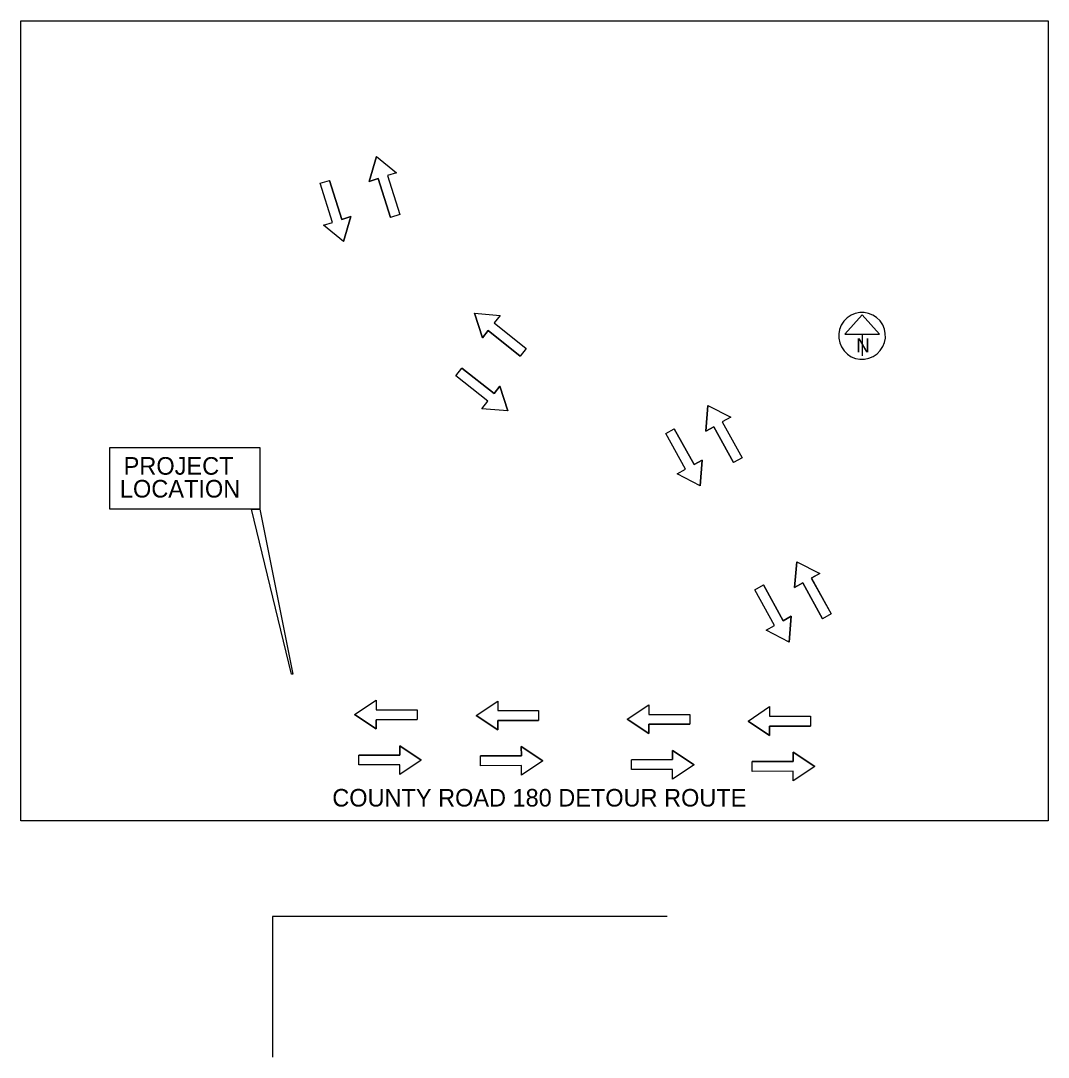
# Model space of a CAD drawing. Extents: x 1633.3 to 1707.6, y 1081.5 to 1106.
# Drawn here: x 1652.62 to 1670.85, y 1081.53 to 1099.94 of the extents above; entities that cross this region are included whole.
import ezdxf

# ---------------------------------------------------------------- set-up
doc = ezdxf.new("R2010")
doc.units = 0
for name, color, linetype in [('SH_Border', 7, 'Continuous'), ('SH_Data', 7, 'Continuous'), ('SH_Text', 7, 'Continuous')]:
    doc.layers.add(name, color=color, linetype=linetype)

msp = doc.modelspace()

# ---------------------------------------------------------------- linework, layer by layer
at = {"layer": 'SH_Border'}
for p, q in [((1664.087, 1084.034), (1657.087, 1084.034)), ((1657.087, 1084.034), (1657.087, 1081.534))]:
    msp.add_line(p, q, dxfattribs=at)
for points in [[(1652.616, 1099.936), (1670.853, 1099.936), (1670.853, 1085.731), (1652.616, 1085.731)], [(1654.195, 1092.36), (1656.86, 1092.36), (1656.86, 1091.264), (1654.195, 1091.264)], [(1656.86, 1091.264), (1657.447, 1088.337), (1657.424, 1088.335), (1656.711, 1091.264)]]:
    msp.add_lwpolyline(points, close=True, dxfattribs=at)
at = {"layer": 'SH_Data'}
for p, q in [((1667.548, 1094.714), (1667.241, 1094.372)), ((1667.856, 1094.372), (1667.548, 1094.714)), ((1667.241, 1094.372), (1667.856, 1094.372)), ((1667.548, 1094.372), (1667.548, 1093.986))]:
    msp.add_line(p, q, dxfattribs=at)
msp.add_arc((1667.548, 1094.34), 0.415, 129.7798, 129.7633, dxfattribs=at)
at = {"layer": 'SH_Text'}
for p, q in [((1658.929, 1097.525), (1658.802, 1097.083)), ((1658.929, 1097.525), (1659.287, 1097.237)), ((1658.802, 1097.083), (1658.958, 1097.133)), ((1658.958, 1097.133), (1659.177, 1096.44)), ((1659.287, 1097.237), (1659.124, 1097.185)), ((1659.124, 1097.185), (1659.342, 1096.493)), ((1657.931, 1097.049), (1658.097, 1097.101)), ((1658.15, 1096.356), (1657.931, 1097.049)), ((1658.316, 1096.409), (1658.097, 1097.101)), ((1658.472, 1096.458), (1658.316, 1096.409)), ((1658.344, 1096.017), (1658.472, 1096.458)), ((1659.342, 1096.493), (1659.177, 1096.44)), ((1657.987, 1096.305), (1658.15, 1096.356)), ((1658.344, 1096.017), (1657.987, 1096.305)), ((1660.668, 1094.742), (1661.126, 1094.704)), ((1660.668, 1094.742), (1660.81, 1094.305)), ((1661.126, 1094.704), (1661.019, 1094.57)), ((1661.019, 1094.57), (1661.588, 1094.119)), ((1660.81, 1094.305), (1660.911, 1094.434)), ((1660.911, 1094.434), (1661.48, 1093.983)), ((1661.588, 1094.119), (1661.48, 1093.983)), ((1660.339, 1093.631), (1660.447, 1093.768)), ((1660.908, 1093.18), (1660.339, 1093.631)), ((1661.016, 1093.317), (1660.447, 1093.768)), ((1661.118, 1093.445), (1661.016, 1093.317)), ((1661.26, 1093.008), (1661.118, 1093.445)), ((1660.802, 1093.046), (1660.908, 1093.18)), ((1664.809, 1093.106), (1664.773, 1092.648)), ((1664.809, 1093.106), (1665.217, 1092.896)), ((1661.26, 1093.008), (1660.802, 1093.046)), ((1665.217, 1092.896), (1665.068, 1092.812)), ((1664.773, 1092.648), (1664.916, 1092.728)), ((1664.916, 1092.728), (1665.269, 1092.093)), ((1665.068, 1092.812), (1665.421, 1092.178)), ((1664.064, 1092.607), (1664.216, 1092.692)), ((1664.417, 1091.973), (1664.064, 1092.607)), ((1664.569, 1092.057), (1664.216, 1092.692)), ((1665.421, 1092.178), (1665.269, 1092.093)), ((1664.268, 1091.89), (1664.417, 1091.973)), ((1664.712, 1092.137), (1664.569, 1092.057)), ((1664.676, 1091.679), (1664.712, 1092.137)), ((1664.676, 1091.679), (1664.268, 1091.89)), ((1666.389, 1090.332), (1666.352, 1089.874)), ((1666.389, 1090.332), (1666.797, 1090.122)), ((1666.352, 1089.874), (1666.495, 1089.954)), ((1666.495, 1089.954), (1666.848, 1089.319)), ((1666.797, 1090.122), (1666.648, 1090.039)), ((1666.648, 1090.039), (1667, 1089.404)), ((1665.644, 1089.834), (1665.796, 1089.918)), ((1665.997, 1089.199), (1665.644, 1089.834)), ((1666.149, 1089.284), (1665.796, 1089.918)), ((1667, 1089.404), (1666.848, 1089.319)), ((1666.292, 1089.363), (1666.149, 1089.284)), ((1666.256, 1088.905), (1666.292, 1089.363)), ((1665.847, 1089.116), (1665.997, 1089.199)), ((1666.256, 1088.905), (1665.847, 1089.116)), ((1658.542, 1087.616), (1658.924, 1087.871)), ((1658.924, 1087.871), (1658.925, 1087.7)), ((1660.699, 1087.603), (1661.081, 1087.858)), ((1661.081, 1087.858), (1661.082, 1087.687)), ((1663.382, 1087.535), (1663.764, 1087.79)), ((1663.764, 1087.79), (1663.765, 1087.619)), ((1665.524, 1087.502), (1665.906, 1087.758)), ((1665.906, 1087.758), (1665.906, 1087.587)), ((1658.542, 1087.616), (1658.925, 1087.363)), ((1658.925, 1087.7), (1659.651, 1087.702)), ((1659.651, 1087.702), (1659.651, 1087.528)), ((1660.699, 1087.603), (1661.082, 1087.349)), ((1661.082, 1087.687), (1661.808, 1087.689)), ((1661.808, 1087.689), (1661.808, 1087.515)), ((1663.765, 1087.619), (1664.491, 1087.621)), ((1664.491, 1087.621), (1664.491, 1087.447)), ((1665.906, 1087.587), (1666.632, 1087.588)), ((1666.632, 1087.588), (1666.633, 1087.414)), ((1658.925, 1087.526), (1659.651, 1087.528)), ((1658.925, 1087.363), (1658.925, 1087.526)), ((1661.082, 1087.513), (1661.808, 1087.515)), ((1661.082, 1087.349), (1661.082, 1087.513)), ((1663.382, 1087.535), (1663.765, 1087.282)), ((1663.765, 1087.445), (1664.491, 1087.447)), ((1663.765, 1087.282), (1663.765, 1087.445)), ((1665.524, 1087.502), (1665.907, 1087.249)), ((1665.907, 1087.413), (1666.633, 1087.414)), ((1665.907, 1087.249), (1665.907, 1087.413)), ((1659.726, 1086.809), (1659.343, 1087.062)), ((1659.343, 1087.062), (1659.344, 1086.899)), ((1661.883, 1086.796), (1661.5, 1087.049)), ((1661.5, 1087.049), (1661.501, 1086.885)), ((1659.344, 1086.899), (1658.618, 1086.897)), ((1658.618, 1086.723), (1658.618, 1086.897)), ((1661.501, 1086.885), (1660.775, 1086.884)), ((1660.775, 1086.71), (1660.775, 1086.884)), ((1664.567, 1086.728), (1664.184, 1086.981)), ((1664.184, 1086.981), (1664.184, 1086.818)), ((1666.708, 1086.695), (1666.325, 1086.949)), ((1666.325, 1086.949), (1666.326, 1086.785)), ((1659.344, 1086.724), (1658.618, 1086.723)), ((1659.345, 1086.554), (1659.344, 1086.724)), ((1659.726, 1086.809), (1659.345, 1086.554)), ((1661.501, 1086.711), (1660.775, 1086.71)), ((1661.502, 1086.54), (1661.501, 1086.711)), ((1661.883, 1086.796), (1661.502, 1086.54)), ((1664.184, 1086.818), (1663.458, 1086.816)), ((1663.458, 1086.642), (1663.458, 1086.816)), ((1664.184, 1086.644), (1663.458, 1086.642)), ((1664.185, 1086.473), (1664.184, 1086.644)), ((1664.567, 1086.728), (1664.185, 1086.473)), ((1666.326, 1086.785), (1665.599, 1086.783)), ((1665.6, 1086.609), (1665.599, 1086.783)), ((1666.708, 1086.695), (1666.326, 1086.44)), ((1666.326, 1086.611), (1665.6, 1086.609)), ((1666.326, 1086.44), (1666.326, 1086.611))]:
    msp.add_line(p, q, dxfattribs=at)
for points in [[(1659.177, 1096.44), (1658.958, 1097.133), (1658.802, 1097.083), (1658.929, 1097.525), (1659.287, 1097.237), (1659.124, 1097.185), (1659.342, 1096.493)], [(1658.097, 1097.101), (1658.316, 1096.409), (1658.472, 1096.458), (1658.344, 1096.017), (1657.987, 1096.305), (1658.15, 1096.356), (1657.931, 1097.049)], [(1661.48, 1093.983), (1660.911, 1094.434), (1660.81, 1094.305), (1660.668, 1094.742), (1661.126, 1094.704), (1661.019, 1094.57), (1661.588, 1094.119)], [(1660.447, 1093.768), (1661.016, 1093.317), (1661.118, 1093.445), (1661.26, 1093.008), (1660.802, 1093.046), (1660.908, 1093.18), (1660.339, 1093.631)], [(1665.269, 1092.093), (1664.916, 1092.728), (1664.773, 1092.648), (1664.809, 1093.106), (1665.217, 1092.896), (1665.068, 1092.812), (1665.421, 1092.178)], [(1664.216, 1092.692), (1664.569, 1092.057), (1664.712, 1092.137), (1664.676, 1091.679), (1664.268, 1091.89), (1664.417, 1091.973), (1664.064, 1092.607)], [(1666.848, 1089.32), (1666.495, 1089.954), (1666.352, 1089.874), (1666.389, 1090.332), (1666.797, 1090.122), (1666.647, 1090.039), (1667, 1089.404)], [(1665.796, 1089.918), (1666.149, 1089.284), (1666.292, 1089.363), (1666.256, 1088.905), (1665.847, 1089.116), (1665.997, 1089.199), (1665.644, 1089.834)], [(1659.651, 1087.528), (1658.925, 1087.526), (1658.925, 1087.363), (1658.542, 1087.616), (1658.924, 1087.871), (1658.925, 1087.7), (1659.651, 1087.702)], [(1661.808, 1087.515), (1661.082, 1087.513), (1661.082, 1087.349), (1660.699, 1087.603), (1661.081, 1087.858), (1661.082, 1087.687), (1661.808, 1087.689)], [(1664.491, 1087.447), (1663.765, 1087.445), (1663.765, 1087.282), (1663.382, 1087.535), (1663.764, 1087.79), (1663.765, 1087.619), (1664.491, 1087.621)], [(1666.633, 1087.414), (1665.907, 1087.413), (1665.907, 1087.249), (1665.524, 1087.502), (1665.906, 1087.758), (1665.906, 1087.587), (1666.632, 1087.588)], [(1658.618, 1086.897), (1659.344, 1086.899), (1659.343, 1087.062), (1659.726, 1086.809), (1659.345, 1086.554), (1659.344, 1086.725), (1658.618, 1086.723)], [(1660.775, 1086.884), (1661.501, 1086.885), (1661.5, 1087.049), (1661.883, 1086.796), (1661.502, 1086.54), (1661.501, 1086.711), (1660.775, 1086.71)], [(1663.458, 1086.816), (1664.184, 1086.818), (1664.184, 1086.981), (1664.567, 1086.728), (1664.185, 1086.473), (1664.184, 1086.644), (1663.458, 1086.642)], [(1665.6, 1086.783), (1666.326, 1086.785), (1666.325, 1086.949), (1666.708, 1086.695), (1666.326, 1086.44), (1666.326, 1086.611), (1665.6, 1086.609)]]:
    msp.add_lwpolyline(points, close=True, dxfattribs=at)

# ---------------------------------------------------------------- texts
at = {"layer": 'SH_Data'}
msp.add_text('N', height=0.25, dxfattribs=at).set_placement((1667.444, 1094.048))
for s, p in [('PROJECT', (1654.443, 1091.876)), ('LOCATION', (1654.376, 1091.471))]:
    msp.add_text(s, height=0.3125, rotation=360, dxfattribs=at).set_placement(p)
at = {"layer": 'SH_Text'}
msp.add_text('COUNTY ROAD 180 DETOUR ROUTE', height=0.312, dxfattribs=at).set_placement((1658.146, 1085.985))

doc.saveas('drawing.dxf')
